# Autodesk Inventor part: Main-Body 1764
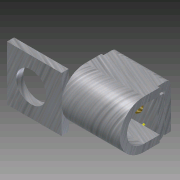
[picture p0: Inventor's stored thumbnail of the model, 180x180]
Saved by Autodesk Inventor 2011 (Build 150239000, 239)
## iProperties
Created: 2008-01
Part Number: Main-Body 1764
Document SubType Name: Modeling
Designer: rlindsay
Density: 1 g/cm^3
Author: rlindsay
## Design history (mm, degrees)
sketch "Sketch1"
  geometry: L1 (-12.629, -4.841)-(0.071, -4.841); L2 (0.071, -4.841)-(0.071, -17.541); L3 (0.071, -17.541)-(-12.629, -17.541); L4 (-12.629, -17.541)-(-12.629, -4.841); C1 r 3.493 at (-6.978, -11.191)
  constraints: 8 end point, 2 parallel, 1 centre point, 1 horizontal, 1 perpendicular
  dimensions: "d0" = 6.985 diameter of C1; "d1" = 12.7 distance between parallel lines of L3 L1; "d2" = 6.35 distance from line of L3 C1.centre (= 0.5 x d1); "d3" = 12.7 distance of L1.start L1.end; "d5" = 7.0485 distance from line of L2 C1.centre (computed from d0)
extrude "Extrusion1" new body sketch "Sketch1" distance "d6" = 1.651; taper "d7" = 0 deg
sketch "Sketch2"
  geometry: L1 (-1.651, 12.7)-(-1.651, 0) reference; L2 (0, 0)-(-1.651, 0) reference; L3 (0, 12.7)-(0, 0) reference; L4 (0, 12.7)-(-1.651, 12.7) reference; L5 (10.795, 1.27)-(10.795, 10.668); L6 (9.525, 11.938)-(3.937, 11.938); L7 (9.271, 1.27)-(9.271, 10.287); L8 (9.271, 10.287)-(3.937, 10.287); L9 (3.937, 2.413)-(7.62, 2.413); L10 (7.62, 2.413)-(7.62, 9.779); L11 (7.62, 9.779)-(9.144, 9.779); L12 (9.144, 9.779)-(9.144, 2.032); L13 (3.937, 0.762)-(7.874, 0.762); L14 (9.271, 1.27)-(10.795, 1.27); A1 r 5.588 centre (3.937, 6.35) between (3.937, 11.938) and (3.937, 0.762); A2 r 3.937 centre (3.937, 6.35) between (3.937, 10.287) and (3.937, 2.413); A3 r 1.27 centre (9.525, 10.668) between (10.795, 10.668) and (9.525, 11.938); A4 r 1.27 centre (7.874, 2.032) between (7.874, 0.762) and (9.144, 2.032)
  constraints: 20 end point, 9 point on circle, 6 perpendicular, 5 parallel, 4 centre point, 2 horizontal, 2 tangent, 1 coincident
  dimensions: "d8" = 11.176 diameter of A1; "d9" = 6.35 distance from line of L4 A1.centre; "d11" = 0 horizontal distance of L8.end A1.centre; "d12" = 0 horizontal distance of A2.centre L6.end; "d13" = 0 horizontal distance of A1.centre L9.start; "d14" = 0 horizontal distance of A1.centre L13.start; "d15" = 1.524 distance between parallel lines of L5 L7; "d16" = 1.524 distance between parallel lines of L10 L12; "d17" = 0.508 distance between parallel lines of L8 L11; "d18" = 0.508 distance between parallel lines of L13 L14; "d19" = 0.127 distance between parallel lines of L12 L7; "d20" = 1.27 radius of A3; "d21" = 1.27 distance from line of L6 A3.centre (= d20); "d22" = 1.27 distance from line of L5 A3.centre (= d20); "d23" = 1.27 radius of A4 (= d20); "d24" = 1.27 distance from line of L13 A4.centre (= d20); "d25" = 1.27 distance from line of L12 A4.centre (= d20); "d26" = 7.62 distance between parallel lines of L3 L10
extrude "Extrusion2" join sketch "Sketch2" distance "d27" = 13.589; taper "d28" = 0 deg
sketch "Sketch3"
  geometry: L1 (-7.62, -0.713)-(-11.884, -0.713); L2 (-11.884, -0.713)-(-11.884, 13.854); L3 (-11.884, 13.854)-(-7.62, 13.854); L4 (-7.62, 13.854)-(-7.62, -0.713); L5 (-7.62, 9.779)-(-7.62, 2.413) reference
  constraints: 8 end point, 2 parallel, 1 horizontal, 1 perpendicular
  dimensions: "d29" = 0 distance between parallel lines of L4 L5
extrude "Extrusion3" cut sketch "Sketch3" distance "d30" = 0.508; taper "d31" = 0 deg
sketch "Sketch4"
  geometry: L1 (7.62, 2.413)-(7.62, 9.779) reference; L2 (7.62, -4.452)-(11.156, -4.452); L3 (11.156, -4.452)-(11.156, 13.283); L4 (11.156, 13.283)-(7.62, 13.283); L5 (7.62, 13.283)-(7.62, -4.452)
  constraints: 8 end point, 2 parallel, 1 horizontal, 1 perpendicular
  dimensions: "d32" = 0 distance between parallel lines of L1 L5
extrude "Extrusion4" cut sketch "Sketch4" distance "d33" = 0.508; taper "d34" = 0 deg
sketch "Sketch5"
  geometry: L1 (0, 10.668)-(-12.573, 10.668) reference; L2 (0, -0.508)-(-12.573, -0.508) reference; C1 r 2.54 at (-6.748, 5.08)
  constraints: 1 centre point
  dimensions: "d35" = 5.588 distance from line of L1 C1.centre; "d36" = 5.588 distance from line of L2 C1.centre (derived); "d37" = 5.08 diameter of C1
extrude "Extrusion5" cut sketch "Sketch5" distance "d38" = 6.35; taper "d39" = 0 deg
thread "Thread1" dims "d40" = 25.4, "d41" = 0
thread "Thread2" dims "d42" = 25.4, "d43" = 0
sketch "Sketch6"
  geometry: A1 r 3.937 centre (3.937, 6.35) between (3.937, 10.287) and (3.937, 2.413) reference
node "+"
body "Solid1"
